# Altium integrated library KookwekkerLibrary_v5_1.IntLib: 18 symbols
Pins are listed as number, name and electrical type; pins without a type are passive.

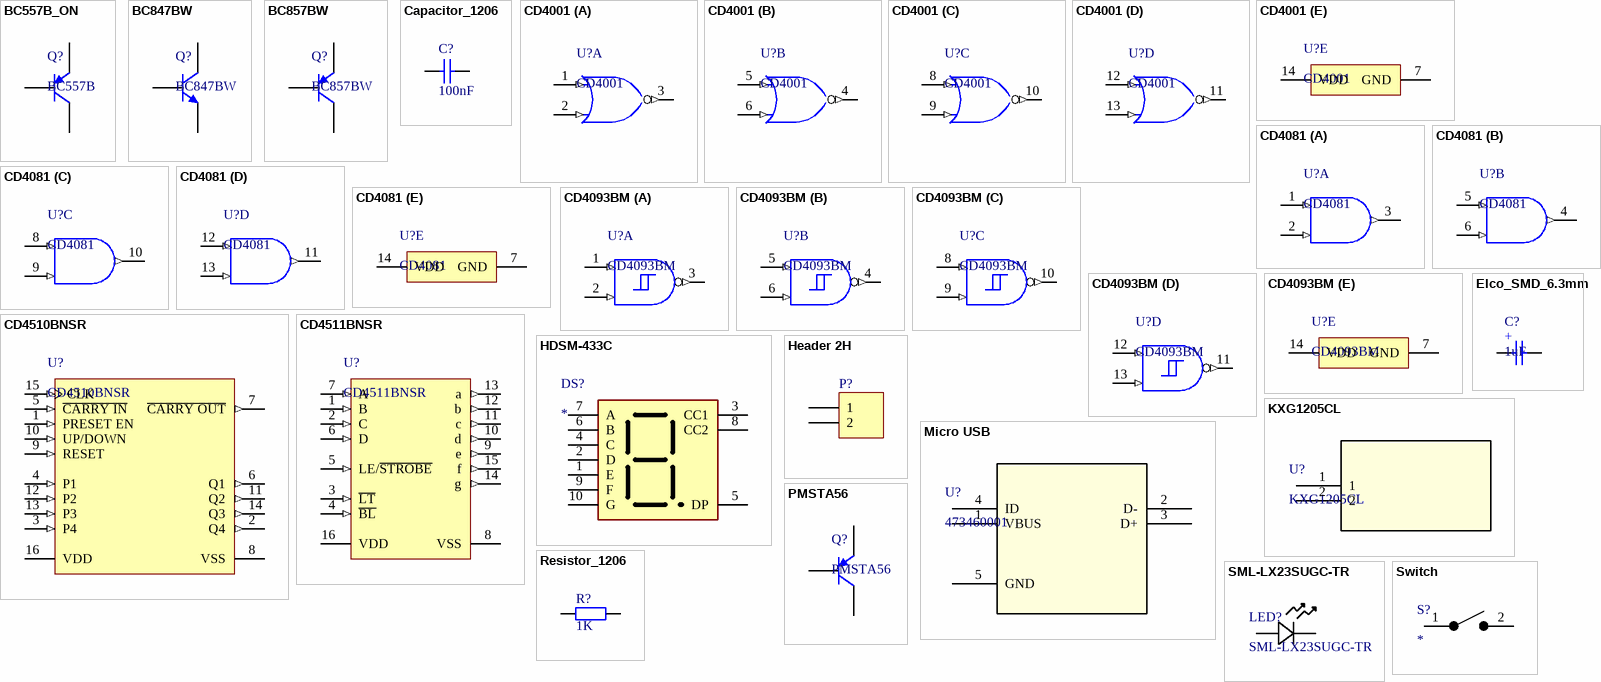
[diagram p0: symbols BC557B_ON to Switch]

## BC557B_ON
designator Q?, comment BC557B
BC857BW
footprint SOT23 (SOT23, 3-Leads, Body 2.92x1.3mm, Pitch 0.95mm)
signal-integrity model BC557BW (ON semiconductor BJT)
simulation model BC557B/ON (Model Description)
pins: 1 B, 2 E, 3 C

## BC847BW
designator Q?
footprint SOT23 (SOT23, 3-Leads, Body 2.92x1.3mm, Pitch 0.95mm)
signal-integrity model BC847BW (Model Description)
simulation model BC847C (Model Description)
pins: 1 B, 2 E, 3 C

## BC857BW
designator Q?
footprint SOT23 (SOT23, 3-Leads, Body 2.92x1.3mm, Pitch 0.95mm)
signal-integrity model BC857BW (Model Description)
simulation model QBC857 (Model Description)
pins: 1 B, 2 E, 3 C

## Capacitor_1206
designator C?, comment 100nF
SMD Capacitor 1206
simulation model CAP (Capacitor)
signal-integrity model Cap
footprint C1206 (Chip Capacitor, Body 3.2x1.6mm, Height 1.7mm, IPC Medium Density)
pins: 1, 2

## CD4001
designator U?
CMOS Quad 2-Input NOR Schmitt Triggers, D0014A, TUBE; Generic Part Number: CD4093B; Manufacturer: Texas Instruments; Output Drive (IOL/IOH)(Max)(mA): 1.5/-1.5; VCC(Min)(V): 3; Rating: Catalog; Schmitt Trigger: Yes; Voltage(Nom)(V): 10; F @ Nom Voltage(Max)(Mhz): 8; ICC @ Nom Voltage(Max)(mA): 0.06; Bits(#): 4; VCC(Max)(V): 18; Technology Family: CD4000
footprint D0014A_N (SOIC, 14-Leads, Body 8.75x4mm, Pitch 1.27mm, IPC Medium Density)
part A pins: 1 A (in), 2 B (in), 3 J (out)
part B pins: 4 K (out), 5 C (in), 6 D (in)
part C pins: 8 E (in), 9 F (in), 10 L (out)
part D pins: 11 M (out), 12 G (in), 13 H (in)
part E pins: 7 GND (power), 14 VDD (power)

## CD4081
designator U?
CMOS Quad 2-Input AND, D0014A, TUBE; Generic Part Number: CD4093B; Manufacturer: Texas Instruments; Output Drive (IOL/IOH)(Max)(mA): 1.5/-1.5; VCC(Min)(V): 3; Rating: Catalog; Schmitt Trigger: Yes; Voltage(Nom)(V): 10; F @ Nom Voltage(Max)(Mhz): 8; ICC @ Nom Voltage(Max)(mA): 0.06; Bits(#): 4; VCC(Max)(V): 18; Technology Family: CD4000
footprint D0014A_N (SOIC, 14-Leads, Body 8.75x4mm, Pitch 1.27mm, IPC Medium Density)
part A pins: 1 A (in), 2 B (in), 3 J (out)
part B pins: 4 K (out), 5 C (in), 6 D (in)
part C pins: 8 E (in), 9 F (in), 10 L (out)
part D pins: 11 M (out), 12 G (in), 13 H (in)
part E pins: 7 GND (power), 14 VDD (power)

## CD4093BM
designator U?
CMOS Quad 2-Input NAND Schmitt Triggers, D0014A, TUBE; Manufacturer: Texas Instruments; Output Drive (IOL/IOH)(Max)(mA): 1.5/-1.5; VCC(Min)(V): 3; Rating: Catalog; Schmitt Trigger: Yes; Voltage(Nom)(V): 10; F @ Nom Voltage(Max)(Mhz): 8; ICC @ Nom Voltage(Max)(mA): 0.06; Bits(#): 4; VCC(Max)(V): 18; Technology Family: CD4000
footprint D0014A_N (SOIC, 14-Leads, Body 8.75x4mm, Pitch 1.27mm, IPC Medium Density)
part A pins: 1 A (in), 2 B (in), 3 J (out)
part B pins: 4 K (out), 5 C (in), 6 D (in)
part C pins: 8 E (in), 9 F (in), 10 L (out)
part D pins: 11 M (out), 12 G (in), 13 H (in)
part E pins: 7 GND (power), 14 VDD (power)

## CD4510BNSR
designator U?
CMOS Presettable BCD Up/Down Counter, NS0016A, LARGE T&R; Manufacturer: Texas Instruments; Bits(#): 4; VCC(Min)(V): 3; Voltage(Nom)(V): 5,10,15; Schmitt Trigger: No; Output Drive (IOL/IOH)(Max)(mA): 1.5/-1.5; Rating: Catalog; Inputs: 1; VCC(Max)(V): 18; Technology Family: CD4000; F @ Nom Voltage(Max)(Mhz): 8; ICC @ Nom Voltage(Max)(mA): 0.03; tpd @ Nom Voltage(Max)(ns): 200
footprint NS0016A_N (SOIC,16-Leads,Body 10.5x5.6mm,Pitch 1.27mm,IPC Medium Density)
pins: 1 PRESET EN (in), 2 Q4 (out), 3 P4 (in), 4 P1 (in), 5 ~{CARRY IN} (in), 6 Q1 (out), 7 ~{CARRY OUT} (out), 8 VSS (power), 9 RESET (in), 10 UP/DOWN (in), 11 Q2 (out), 12 P2 (in), 13 P3 (in), 14 Q3 (out), 15 CLK (in), 16 VDD (power)

## CD4511BNSR
designator U?
CMOS BCD-to-7-Segment LED Latch / Decoder / Driver, 3 to 18 V, -55 to 125 degC, 16-pin SOP (NS16), Green (RoHS & no Sb/Br); Manufacturer: Texas Instruments; Vin(Max)(V): 18; Rating: Military; Vin(Min)(V): 3; SubFamily: Discrete Segment LED Driver
footprint TI-NS16_N (SOP, 16-Leads, Body 10.2x5.3mm, Pitch 1.27mm, IPC Medium Density)
pins: 1 B (in), 2 C (in), 3 ~{LT} (in), 4 ~{BL} (in), 5 LE/~{STROBE} (in), 6 D (in), 7 A (in), 8 VSS (power), 9 e (out), 10 d (out), 11 c (out), 12 b (out), 13 a (out), 14 g (out), 15 f (out), 16 VDD (power)

## Elco_SMD_6.3mm
designator C?, comment 1uF
Elco SMD 6.3mm
footprint CAP_ELEC_6.3x4.2 (Capacitor, polarized, aluminum can; 6.3x4.2mm DxH)
simulation model Model Name (Model Description)
pins: 1, 2

## HDSM-433C
designator DS?
Display; Manufacturer_Name: Avago Technologies; Manufacturer_Part_Number: HDSM-433C
footprint HDSM433C
pins: 1 E, 2 D, 3 CC1, 4 C, 5 DP, 6 B, 7 A, 8 CC2, 9 F, 10 G

## Header 2H
designator P?
Header, 2-Pin, Right Angle
footprint HDR1X2H (Connector; Header; 2 Position; Right Angle)
signal-integrity model Connector
pins: 1, 2

## KXG1205CL
designator U?
Buzzer 9V; Mfr_Name: Kingstate
footprint KXG1205CL_KNS
pins: 1, 2

## Micro USB
designator U?, comment 473460001
micro USB connector type 473460001; Mfr_Name: Molex Connector Corporation
footprint 47346-0001_MOL
pins: 1 VBUS, 2 D-, 3 D+, 4 ID, 5 GND

## PMSTA56
designator Q?
footprint SOT23 (SOT23, 3-Leads, Body 2.92x1.3mm, Pitch 0.95mm)
signal-integrity model PMSTA56 (ON semiconductor BJT)
simulation model QPMSTA56/NXP (Model Description)
pins: 1 B, 2 E, 3 C

## Resistor_1206
designator R?, comment 1K
SMD Resistor 1206
simulation model RESISTOR (Resistor)
signal-integrity model Res
footprint R1206 (Chip Resistor, Body 3.2x1.6mm, IPC Medium Density)
pins: 1, 2

## SML-LX23SUGC-TR
designator LED?
Yellow LED SMD; Mfr_Name: Lumex; Type: DEV
footprint LED_SML-LX23SUGC-TR_LUM
simulation model SMLLX23SUGCTR_yellowLED (Model Description)
pins: 1, 2

## Switch
designator S?
Switch; Manufacturer_Name: TE Connectivity; Manufacturer_Part_Number: 147873-1
footprint 1478731
pins: 1, 2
